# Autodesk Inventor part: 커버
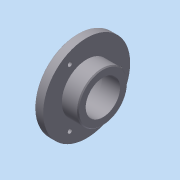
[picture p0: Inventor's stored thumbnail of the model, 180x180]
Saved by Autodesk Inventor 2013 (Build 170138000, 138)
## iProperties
Company: 한국ATC센터
Created: 2014-10
Part Number: 커버
Document SubType Name: Modeling
Designer: 한국ATC센터
Density: 2.71 g/cm^3
Material: 알루미늄 6061
Mass: 189.975 g
Surface Area: 197.126 cm^2
Volume: 70.1013 cm^3
Author: KYOUNG IL JANG
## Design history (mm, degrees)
sketch "스케치1"
  geometry: L1 (-13.5, 0)-(13.5, 0); L2 (-13.5, 0)-(-13.5, 45.5); L3 (-13.5, 45.5)-(-3.5, 45.5); L4 (-3.5, 45.5)-(-3.5, 26); L5 (-3.5, 26)-(13.5, 26); L6 (13.5, 26)-(13.5, 0); 2 further points
  constraints: 12 end point, 3 parallel, 2 perpendicular, 1 coincident, 1 horizontal, 1 midpoint
  dimensions: "d0" = 27 distance of L1.start L1.end; "d1" = 91 diameter of L3 L1; "d2" = 52 diameter of L5 L1; "d3" = 10 distance of L2.end L3.end
revolve "회전1" sketch "스케치1" stored, may be unused: angle "d4" = 90 deg
hole "구멍1" diameter "d7" = 36; stored, may be unused: countersink angle "d11" = 90 deg, drill point angle "d13" = 118 deg; dims "d5" = 10, "d6" = 10, "d8" = 6, "d9" = 40, "d10" = 8.3, "d12" = 8
sketch "스케치2"
  geometry: 2 further points
  constraints: 1 vertical alignment
  dimensions: "d14" = 35 distance of point (0, 0) point (0, 35)
hole "구멍2" sketch "스케치2" at (0, 35) diameter "d15" = 4.5; stored, may be unused: countersink angle "d19" = 90 deg, drill point angle "d21" = 118 deg; dims "d16" = 6, "d17" = 8, "d18" = 4.4, "d20" = 8
chamfer "모따기1" distance "d25" = 0.8; stored, may be unused: second distance "d26" = 2, angle "d27" = 30 deg
fillet "모깎기1" dims "d28" = 0.1, "d29" = 3
chamfer "모따기2" distance "d30" = 1; stored, may be unused: second distance "d31" = 2, angle "d32" = 30 deg
node "솔리드1"
pattern_circular "원형 패턴1" dims angle "d23" = 360 deg
